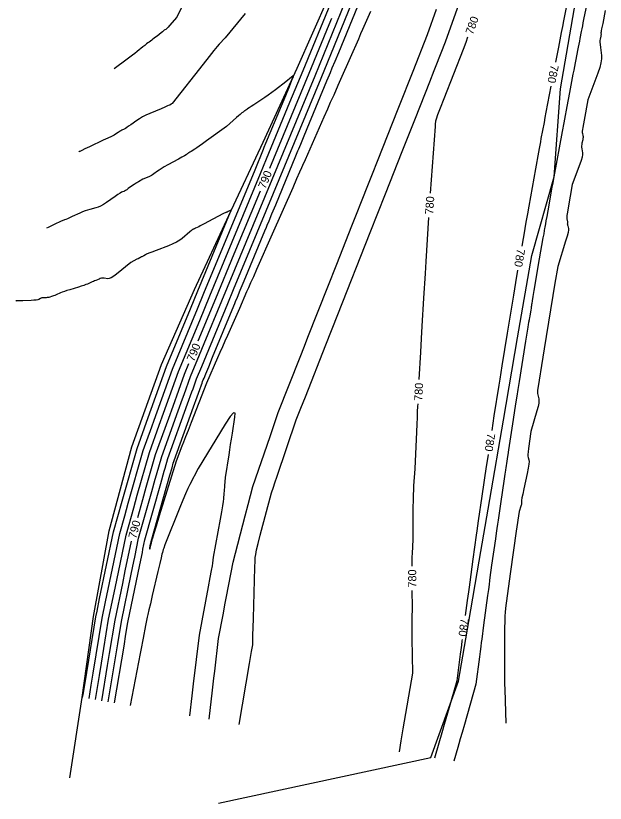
# Model space of a CAD drawing. Extents: x -26 to 1809989, y -25 to 828749.
# Drawn here: x 1809519.1 to 1809881.8, y 826839.3 to 827324 of the extents above; entities that cross this region are included whole.
import ezdxf

# ---------------------------------------------------------------- set-up
doc = ezdxf.new("R2010")
doc.units = 0
for name, color, linetype in [('DESIGN - CONTOURS - Index with Text', 7, 'Continuous'), ('DESIGN - CONTOURS - Intermediate with optional Text', 7, 'Continuous'), ('DESIGN - ROW - Slope Lines', 7, 'Continuous')]:
    doc.layers.add(name, color=color, linetype=linetype)

msp = doc.modelspace()

# ---------------------------------------------------------------- linework, layer by layer
at = {"layer": 'DESIGN - CONTOURS - Index with Text'}
for points in [[(1809870.88, 827393.4), (1809869.78, 827388.6), (1809867.7, 827378.36), (1809867.16, 827375.72), (1809866.44, 827372.18), (1809864.45, 827362.41), (1809858.96, 827335.44), (1809856.09, 827320.79), (1809855.43, 827317.43), (1809854.68, 827313.61), (1809852.93, 827304.59), (1809851.13, 827295.37)], [(1809624.52, 827336.19), (1809618.16, 827323.09), (1809613.69, 827318), (1809612.83, 827317.03), (1809612.15, 827316.3), (1809611.66, 827315.82), (1809611.35, 827315.57), (1809610.78, 827315.23), (1809610.48, 827315.03), (1809610, 827314.67), (1809609.33, 827314.15), (1809608.49, 827313.48), (1809606, 827311.48), (1809605.1, 827310.76), (1809604.28, 827310.12), (1809603.53, 827309.55), (1809602.86, 827309.06), (1809601.17, 827307.84), (1809600.45, 827307.3), (1809599.57, 827306.62), (1809598.51, 827305.77), (1809597.27, 827304.78), (1809593.77, 827301.93), (1809592.4, 827300.83), (1809590.92, 827299.69), (1809589.35, 827298.51), (1809587.67, 827297.28), (1809579.57, 827291.43)], [(1809675.33, 827230.16), (1809699.53, 827288.67), (1809711.85, 827318.62), (1809713.49, 827322.6)], [(1809774.31, 827214.89), (1809777.26, 827255.78), (1809777.37, 827257.13), (1809777.54, 827259.23), (1809777.89, 827260.46), (1809778.86, 827263.19), (1809780.47, 827267.42), (1809782.7, 827273.15), (1809794.58, 827303.37), (1809796.14, 827307.75), (1809797.34, 827311.12)], [(1809848.26, 827280.65), (1809845.29, 827264.67), (1809844.66, 827261.29), (1809844.11, 827258.32), (1809842.26, 827248.42), (1809841.9, 827246.44), (1809841.52, 827244.39), (1809841.12, 827242.28), (1809840.72, 827240.1), (1809838.81, 827229.75), (1809834.72, 827206.74), (1809833.89, 827202.09), (1809833.17, 827198.02), (1809832.55, 827194.52), (1809832.03, 827191.59), (1809830.38, 827182.26)], [(1809631.4, 827123.89), (1809642.2, 827150.05), (1809653.51, 827177.41), (1809669.6, 827216.3)], [(1809767.38, 827100.1), (1809768.32, 827117.05), (1809768.77, 827125.29), (1809769.19, 827132.97), (1809770.14, 827150.22), (1809771.1, 827165.43), (1809771.55, 827172.66), (1809773.26, 827199.93)], [(1809827.87, 827167.47), (1809826.6, 827159.9), (1809825.92, 827155.84), (1809825.27, 827151.95), (1809824.65, 827148.24), (1809821.36, 827128.55), (1809818.18, 827108.51), (1809817.51, 827104.34), (1809816.89, 827100.4), (1809816.3, 827096.71), (1809813.28, 827077.68), (1809811.93, 827068.75)], [(1809594.14, 827015.2), (1809597.26, 827026.23), (1809599.4, 827033.82), (1809605.1, 827054), (1809613.18, 827076.38), (1809615.86, 827083.81), (1809622.97, 827103.48), (1809625.67, 827110.02)], [(1809762.98, 826985.21), (1809762.99, 826988.14), (1809763.04, 826990.96), (1809763.12, 826993.13), (1809763.54, 827001.76), (1809763.68, 827021.65), (1809763.73, 827025.65), (1809763.81, 827029.16), (1809763.92, 827032.17), (1809764.06, 827034.67), (1809764.81, 827045.2), (1809765.79, 827067.97), (1809766, 827072.61), (1809766.19, 827076.75), (1809766.36, 827080.4), (1809766.52, 827083.56), (1809766.6, 827085.12)], [(1809809.7, 827053.92), (1809809.14, 827050.17), (1809808.6, 827046.59), (1809805.86, 827028.32), (1809803.68, 827013.2), (1809803.23, 827010.05), (1809802.8, 827007.06), (1809802.4, 827004.25), (1809800.3, 826989.64), (1809798.39, 826975.41), (1809797.98, 826972.42), (1809797.6, 826969.53), (1809797.22, 826966.75), (1809796.86, 826964.07), (1809795.63, 826954.92)], [(1809572.06, 826902.41), (1809575.61, 826924.05), (1809576.83, 826931.48), (1809580.18, 826951.94), (1809584.87, 826974.66), (1809586.47, 826982.38), (1809590.26, 827000.72)], [(1809755.13, 826870.91), (1809756.31, 826877.84), (1809757.55, 826885.12), (1809763.39, 826919.43), (1809763.02, 826940.68), (1809762.95, 826944.85), (1809762.92, 826948.27), (1809762.92, 826950.93), (1809762.95, 826952.83), (1809763.16, 826959.94), (1809763.08, 826970.21)], [(1809793.69, 826940.04), (1809793.6, 826939.33), (1809793.25, 826936.62), (1809792.89, 826933.85), (1809792.53, 826931.03), (1809790.41, 826914.63), (1809785.75, 826898.36), (1809784.74, 826894.85), (1809783.73, 826891.31), (1809782.71, 826887.73), (1809781.67, 826884.12), (1809776.82, 826867.18)]]:
    msp.add_lwpolyline(points, dxfattribs=at)
at = {"layer": 'DESIGN - CONTOURS - Intermediate with optional Text'}
for points in [[(1809656.58, 826887.87), (1809662.97, 826925.42), (1809664.22, 826932.77), (1809664.93, 826936.9), (1809664.89, 826938.94), (1809664.91, 826940.16), (1809664.98, 826942.94), (1809665.1, 826947.28), (1809665.27, 826953.19), (1809666.2, 826984.39), (1809666.19, 826984.81), (1809666.2, 826985.04), (1809666.22, 826985.55), (1809666.31, 826987.42), (1809666.47, 826990.65), (1809666.71, 826992.42), (1809667.3, 826995.28), (1809668.24, 826999.24), (1809669.54, 827004.3), (1809676.44, 827030.48), (1809677.6, 827033.89), (1809678.5, 827036.53), (1809679.89, 827040.61), (1809691.71, 827075.24), (1809694.56, 827082.48), (1809697.29, 827089.4), (1809709.9, 827121.41), (1809717.28, 827140.1), (1809737.2, 827190.53), (1809746.65, 827214.44), (1809756.94, 827240.49), (1809765.02, 827260.96), (1809773.77, 827283.23), (1809776.54, 827290.27), (1809777.79, 827293.47), (1809783.47, 827307.9), (1809793.98, 827337.47)], [(1809568.11, 826903.09), (1809570.57, 826918.04), (1809571.79, 826925.47), (1809576.24, 826952.64), (1809579.61, 826968.93), (1809581.21, 826976.69), (1809586.94, 827004.38), (1809591.7, 827021.25), (1809593.85, 827028.88), (1809601.3, 827055.26), (1809607.36, 827072.02), (1809610.05, 827079.48), (1809619.27, 827105), (1809632.26, 827136.46), (1809638.51, 827151.61), (1809652.27, 827184.87), (1809669.68, 827226.96), (1809673.43, 827236.04), (1809687.78, 827270.72), (1809695.85, 827290.23), (1809712.96, 827331.83)], [(1809576, 826901.73), (1809580.65, 826930.07), (1809581.86, 826937.49), (1809584.12, 826951.24), (1809590.14, 826980.39), (1809591.73, 826988.07), (1809592.31, 826990.88), (1809594.69, 827002.42), (1809602.82, 827031.21), (1809604.95, 827038.75), (1809605.72, 827041.51), (1809608.9, 827052.75), (1809619.01, 827080.75), (1809621.67, 827088.13), (1809622.65, 827090.84), (1809626.67, 827101.96), (1809632.14, 827115.22), (1809635.03, 827122.2), (1809645.88, 827148.49), (1809703.22, 827287.11), (1809722.06, 827332.93)], [(1809579.94, 826901.06), (1809585.69, 826936.08), (1809586.9, 826943.5), (1809588.06, 826950.54), (1809595.41, 826986.12), (1809596.98, 826993.76), (1809597.37, 826995.64), (1809598.57, 827001.45), (1809608.37, 827036.18), (1809610.49, 827043.69), (1809611.03, 827045.58), (1809612.7, 827051.5), (1809624.83, 827085.11), (1809627.49, 827092.45), (1809628.17, 827094.35), (1809630.37, 827100.44), (1809633.53, 827108.1), (1809636.41, 827115.07), (1809649.56, 827146.94), (1809653.13, 827155.54), (1809677.63, 827214.79), (1809706.9, 827285.55), (1809725.76, 827331.42)], [(1809737.37, 827326.69), (1809732.43, 827315.46), (1809731.26, 827312.81), (1809729.87, 827309.64), (1809728.26, 827305.97), (1809726.42, 827301.8), (1809717.34, 827281.13), (1809714.72, 827275.21), (1809713.92, 827273.4), (1809712.64, 827270.51), (1809710.89, 827266.54), (1809708.65, 827261.49), (1809697.12, 827235.4), (1809695.56, 827231.88), (1809694.93, 827230.45), (1809693.71, 827227.69), (1809691.9, 827223.59), (1809689.5, 827218.15), (1809676.9, 827189.66), (1809667.21, 827167.73), (1809665.27, 827163.35), (1809663.61, 827159.6), (1809662.24, 827156.49), (1809661.14, 827154.01), (1809656.68, 827143.92), (1809649.33, 827127.25), (1809647.77, 827123.71), (1809646.24, 827120.23), (1809644.73, 827116.82), (1809643.25, 827113.46), (1809636.41, 827097.96), (1809626.97, 827073.59), (1809625.1, 827068.77), (1809623.55, 827064.75), (1809622.3, 827061.55), (1809621.37, 827059.15), (1809617.76, 827049.83), (1809607.42, 827016.2), (1809605.48, 827009.87), (1809604.07, 827005.29), (1809603.2, 827002.46), (1809602.87, 827001.38), (1809602.58, 827000.44), (1809602.43, 826999.79), (1809602.38, 826999.59), (1809602.3, 826999.24), (1809602.19, 826998.75), (1809602.05, 826998.13), (1809601.62, 826996.28), (1809601.5, 826995.78), (1809601.47, 826995.65), (1809601.51, 826995.91), (1809601.64, 826996.54), (1809602.09, 826998.73), (1809602.24, 826999.45), (1809602.35, 826999.97), (1809602.41, 827000.29), (1809602.44, 827000.4), (1809602.45, 827000.47), (1809612.12, 827034.72), (1809613.93, 827041.16), (1809615.24, 827045.79), (1809616.04, 827048.63), (1809616.33, 827049.65), (1809616.5, 827050.25), (1809628.42, 827083.26), (1809630.66, 827089.48), (1809632.29, 827093.98), (1809633.3, 827096.78), (1809633.69, 827097.86), (1809634.07, 827098.92), (1809634.49, 827099.94), (1809634.92, 827100.97), (1809636.02, 827103.64), (1809637.8, 827107.94), (1809640.24, 827113.88), (1809653.25, 827145.38), (1809653.9, 827146.96), (1809654.37, 827148.08), (1809655.48, 827150.76), (1809657.23, 827155.01), (1809659.64, 827160.82), (1809672.36, 827191.58), (1809673.3, 827193.85), (1809673.81, 827195.08), (1809674.93, 827197.8), (1809676.67, 827202.01), (1809679.03, 827207.71), (1809691.47, 827237.79), (1809692.72, 827240.81), (1809693.28, 827242.16), (1809694.42, 827244.92), (1809696.15, 827249.09), (1809698.46, 827254.67), (1809710.58, 827283.99), (1809712.1, 827287.69), (1809712.7, 827289.14), (1809713.84, 827291.92), (1809715.53, 827296.03), (1809717.77, 827301.46), (1809729.47, 827329.91)], [(1809870.37, 827331.35), (1809868.48, 827321.68), (1809868.09, 827319.67), (1809867.72, 827317.76), (1809867.37, 827315.97), (1809867.04, 827314.3), (1809866.2, 827309.98), (1809865.87, 827308.3), (1809865.53, 827306.52), (1809865.16, 827304.62), (1809864.76, 827302.61), (1809863.69, 827297.1), (1809863.28, 827294.99), (1809862.85, 827292.79), (1809862.41, 827290.5), (1809861.94, 827288.12), (1809859.75, 827276.81), (1809858.15, 827268.25), (1809857.72, 827265.9), (1809857.09, 827262.52), (1809856.28, 827258.12), (1809855.27, 827252.69), (1809850.14, 827224.95), (1809850.08, 827224.58), (1809850.06, 827224.48), (1809850.04, 827224.35), (1809850.01, 827224.19), (1809849.97, 827223.99), (1809849.87, 827223.41), (1809849.75, 827222.71), (1809849.45, 827221.05), (1809848.99, 827218.43), (1809848.35, 827214.85), (1809846.43, 827204.02), (1809845.79, 827200.41), (1809845.31, 827197.7), (1809845, 827195.9), (1809844.84, 827195), (1809844.63, 827193.82), (1809844.5, 827193.08), (1809844.26, 827191.77), (1809843.93, 827189.87), (1809843.49, 827187.38), (1809841.2, 827174.44), (1809837.94, 827154.92), (1809837.33, 827151.24), (1809836.88, 827148.56), (1809836.6, 827146.89), (1809836.49, 827146.23), (1809836.42, 827145.79), (1809836.37, 827145.48), (1809836.27, 827144.88), (1809836.12, 827143.98), (1809835.92, 827142.79), (1809835.32, 827139.22), (1809835.12, 827138.03), (1809834.98, 827137.17), (1809834.89, 827136.61), (1809834.85, 827136.37), (1809834.81, 827136.15), (1809834.76, 827135.85), (1809834.64, 827135.11), (1809834.44, 827133.93), (1809834.17, 827132.31), (1809832.74, 827123.73), (1809828.81, 827098.95), (1809828.03, 827094.01), (1809827.36, 827089.82), (1809826.82, 827086.38), (1809826.39, 827083.68), (1809824.68, 827072.85), (1809822.29, 827056.92), (1809821.83, 827053.85), (1809821.47, 827051.47), (1809821.21, 827049.76), (1809821.06, 827048.74), (1809820.79, 827046.93), (1809820.64, 827045.93), (1809820.39, 827044.27), (1809820.05, 827041.96), (1809819.6, 827038.99), (1809817.3, 827023.62), (1809815.85, 827013.5), (1809815.52, 827011.17), (1809815.14, 827008.5), (1809814.71, 827005.5), (1809814.23, 827002.16), (1809811.89, 826985.82), (1809810.88, 826978.29), (1809810.62, 826976.39), (1809810.29, 826973.91), (1809809.87, 826970.85), (1809809.38, 826967.21), (1809806.92, 826948.9), (1809805.81, 826940.32), (1809805.54, 826938.26), (1809805.22, 826935.76), (1809804.84, 826932.81), (1809804.4, 826929.41), (1809802.23, 826912.54), (1809795.14, 826887.82), (1809793.75, 826882.96), (1809792.61, 826878.97), (1809791.72, 826875.85), (1809791.07, 826873.6), (1809788.65, 826865.15)], [(1809660.17, 827325.41), (1809648.02, 827310.46), (1809644.15, 827306.41), (1809642.91, 827305.01), (1809640.86, 827302.51), (1809638, 827298.94), (1809634.33, 827294.28), (1809615.28, 827270.02), (1809614.58, 827269.49), (1809614.44, 827269.39), (1809614.33, 827269.31), (1809614.26, 827269.26), (1809614.21, 827269.23), (1809614.12, 827269.2), (1809614.09, 827269.18), (1809614.05, 827269.17), (1809614.02, 827269.15), (1809613.89, 827269.07), (1809613.53, 827268.92), (1809612.53, 827268.49), (1809610.89, 827267.79), (1809608.6, 827266.81), (1809601.64, 827263.86), (1809599.18, 827262.76), (1809597.02, 827261.69), (1809595.16, 827260.63), (1809593.59, 827259.6), (1809589.82, 827256.89), (1809588.51, 827255.96), (1809587.42, 827255.22), (1809586.54, 827254.65), (1809585.87, 827254.27), (1809584.39, 827253.5), (1809583.83, 827253.2), (1809583.26, 827252.87), (1809582.68, 827252.52), (1809582.1, 827252.14), (1809580.52, 827251.11), (1809579.61, 827250.58), (1809578.04, 827249.78), (1809575.83, 827248.7), (1809572.96, 827247.34), (1809564.46, 827243.36), (1809561.66, 827242.05), (1809559.66, 827241.11), (1809558.45, 827240.55), (1809558.04, 827240.35), (1809557.94, 827240.29)], [(1809637.99, 826891.07), (1809640.12, 826908.94), (1809641, 826916.38), (1809641.5, 826920.54), (1809643.9, 826940.63), (1809646.66, 826955.31), (1809647.99, 826962.38), (1809648.8, 826966.65), (1809652.79, 826987.77), (1809660.31, 827016.27), (1809662.14, 827023.24), (1809665.04, 827034.24), (1809675.55, 827064.97), (1809677.88, 827071.81), (1809680.61, 827079.8), (1809694.01, 827113.8), (1809696.74, 827120.74), (1809698.85, 827126.09), (1809711.13, 827157.17), (1809716.64, 827171.13), (1809725.94, 827194.67), (1809729.18, 827202.89), (1809731.45, 827208.62), (1809736.58, 827221.61), (1809738.17, 827225.63), (1809742.09, 827235.57), (1809753.97, 827265.64), (1809758.01, 827275.91), (1809760.25, 827281.62), (1809763.52, 827289.95), (1809772.35, 827312.43), (1809777.92, 827328.08)], [(1809881.79, 827327.27), (1809880.22, 827319.21), (1809879.58, 827315.91), (1809879.37, 827314.81), (1809879.23, 827314), (1809879.16, 827313.46), (1809879.15, 827313.21), (1809879.21, 827312.92), (1809879.21, 827312.74), (1809879.18, 827312.42), (1809879.1, 827311.96), (1809878.99, 827311.36), (1809878.63, 827309.59), (1809878.54, 827308.77), (1809878.54, 827307.66), (1809878.64, 827306.25), (1809878.82, 827304.54), (1809879.44, 827299.58), (1809879.47, 827297.51), (1809879.12, 827295.02), (1809878.38, 827292.1), (1809877.25, 827288.76), (1809871.09, 827272.19), (1809868.79, 827259.78), (1809867.93, 827255.13), (1809867.74, 827253.97), (1809867.65, 827253), (1809867.64, 827252.22), (1809867.72, 827251.62), (1809868.06, 827250.29), (1809868.15, 827249.76), (1809868.16, 827249.15), (1809868.09, 827248.46), (1809867.94, 827247.7), (1809867.44, 827245.57), (1809867.3, 827244.76), (1809867.24, 827243.92), (1809867.27, 827243.05), (1809867.38, 827242.15), (1809867.81, 827239.71), (1809867.82, 827238.58), (1809867.55, 827237.01), (1809866.98, 827235.01), (1809866.13, 827232.57), (1809861.48, 827220.16), (1809858.95, 827205.85), (1809858.49, 827203.11), (1809858.2, 827201.05), (1809858.07, 827199.66), (1809858.11, 827198.94), (1809858.43, 827197.91), (1809858.53, 827197.54), (1809858.59, 827197.23), (1809858.61, 827196.96), (1809858.59, 827196.74), (1809858.47, 827196.23), (1809858.46, 827195.98), (1809858.49, 827195.65), (1809858.58, 827195.21), (1809858.73, 827194.68), (1809859.17, 827193.14), (1809859.19, 827192.21), (1809858.91, 827190.6), (1809858.32, 827188.28), (1809857.43, 827185.28), (1809852.56, 827169.64), (1809850.85, 827159.38), (1809844.13, 827118.92), (1809843.33, 827113.92), (1809840.26, 827094.5), (1809840.14, 827093.47), (1809840.12, 827092.48), (1809840.19, 827091.53), (1809840.36, 827090.61), (1809840.92, 827088.21), (1809841.01, 827087.07), (1809840.84, 827085.48), (1809840.43, 827083.42), (1809839.77, 827080.89), (1809836.08, 827068.03), (1809834.53, 827057.65), (1809834.27, 827055.64), (1809834.14, 827054.04), (1809834.15, 827052.87), (1809834.29, 827052.11), (1809834.86, 827050.65), (1809834.95, 827049.72), (1809834.79, 827048.03), (1809834.39, 827045.58), (1809833.75, 827042.37), (1809831.71, 827032.78), (1809831.04, 827029.6), (1809830.57, 827027.23), (1809830.3, 827025.68), (1809830.22, 827024.95), (1809830.29, 827024.09), (1809830.28, 827023.72), (1809830.21, 827023.26), (1809830.07, 827022.72), (1809829.86, 827022.08), (1809828.75, 827018.92), (1809827.01, 827006.72), (1809823.48, 826982), (1809820.85, 826962.49), (1809820.46, 826959.43), (1809820.17, 826956.8), (1809819.99, 826954.61), (1809819.91, 826952.85), (1809819.77, 826945.66), (1809819.8, 826937.49), (1809819.89, 826912.73), (1809819.91, 826909.4), (1809820.55, 826888.55)], [(1809564.17, 826903.77), (1809565.53, 826912.02), (1809566.75, 826919.46), (1809572.31, 826953.34), (1809574.34, 826963.2), (1809575.96, 826971.01), (1809583.06, 827005.36), (1809586.14, 827016.27), (1809588.31, 827023.95), (1809597.5, 827056.51), (1809602.72, 827070.94), (1809604.24, 827075.16), (1809615.57, 827106.52), (1809630.87, 827143.59), (1809634.83, 827153.17), (1809666.3, 827229.25), (1809671.51, 827241.85), (1809672.03, 827243.12), (1809673.05, 827245.58), (1809685.18, 827274.9), (1809687.45, 827280.39), (1809689.04, 827284.3), (1809689.97, 827286.62), (1809690.23, 827287.37), (1809690.04, 827287.23), (1809689.68, 827286.95), (1809688.75, 827286.22), (1809685.17, 827283.42), (1809678.87, 827278.48), (1809676.57, 827276.71), (1809674.4, 827275.11), (1809672.37, 827273.67), (1809670.46, 827272.39), (1809665.56, 827269.2), (1809663.91, 827268.12), (1809662.63, 827267.29), (1809661.74, 827266.69), (1809661.23, 827266.33), (1809660.04, 827265.45), (1809659.72, 827265.21), (1809659.4, 827264.98), (1809659.09, 827264.76), (1809658.27, 827264.16), (1809657.83, 827263.81), (1809657.13, 827263.23), (1809656.18, 827262.41), (1809654.97, 827261.36), (1809648.71, 827255.87), (1809636.39, 827246.94), (1809633.97, 827245.19), (1809631.98, 827243.78), (1809630.43, 827242.71), (1809629.32, 827241.98), (1809626.94, 827240.49), (1809626.14, 827239.99), (1809625.55, 827239.61), (1809625.16, 827239.36), (1809624.97, 827239.24), (1809624.73, 827239.07), (1809624.65, 827239), (1809624.57, 827238.94), (1809624.49, 827238.87), (1809624.41, 827238.8), (1809624.22, 827238.61), (1809623.85, 827238.38), (1809622.89, 827237.83), (1809621.34, 827236.97), (1809619.2, 827235.78), (1809612.7, 827232.19), (1809610.47, 827230.94), (1809608.65, 827229.87), (1809607.24, 827228.99), (1809606.23, 827228.3), (1809604.1, 827226.7), (1809603.3, 827226.13), (1809602.51, 827225.63), (1809601.72, 827225.2), (1809600.94, 827224.84), (1809597.32, 827223.33), (1809594.66, 827221.82), (1809594.16, 827221.54), (1809593.77, 827221.33), (1809593.52, 827221.19), (1809593.38, 827221.13), (1809593.18, 827221.06), (1809592.99, 827220.94), (1809592.56, 827220.65), (1809591.9, 827220.19), (1809591, 827219.54), (1809588.28, 827217.59), (1809587.34, 827216.93), (1809586.58, 827216.44), (1809586, 827216.09), (1809585.59, 827215.91), (1809584.72, 827215.63), (1809584.19, 827215.37), (1809583.25, 827214.79), (1809581.91, 827213.91), (1809580.15, 827212.71), (1809574.92, 827209.1), (1809573.03, 827207.87), (1809571.3, 827206.9), (1809569.72, 827206.18), (1809568.3, 827205.72), (1809564.7, 827204.83), (1809563.3, 827204.44), (1809561.79, 827203.93), (1809560.19, 827203.29), (1809558.48, 827202.53), (1809553.8, 827200.35), (1809552.19, 827199.61), (1809550.88, 827199.02), (1809549.88, 827198.59), (1809549.17, 827198.31), (1809547.69, 827197.78), (1809547.06, 827197.53), (1809546.28, 827197.2), (1809545.36, 827196.78), (1809544.29, 827196.28), (1809538.93, 827193.74), (1809538.08, 827193.35)], [(1809560.23, 826904.45), (1809560.49, 826906.01), (1809561.71, 826913.45), (1809568.37, 826954.04), (1809569.08, 826957.47), (1809570.7, 826965.32), (1809579.18, 827006.34), (1809584.51, 827025.21), (1809593.7, 827057.76), (1809600.58, 827076.8), (1809611.87, 827108.04), (1809626.6, 827143.71), (1809631.14, 827154.73), (1809651.26, 827203.36), (1809651.44, 827203.82), (1809651.56, 827204.13), (1809651.61, 827204.31), (1809651.6, 827204.35), (1809651.48, 827204.28), (1809651.4, 827204.25), (1809651.27, 827204.19), (1809651.08, 827204.11), (1809650.1, 827203.69), (1809649.85, 827203.59), (1809649.64, 827203.49), (1809649.47, 827203.42), (1809649.35, 827203.35), (1809649.09, 827203.21), (1809648.97, 827203.14), (1809648.8, 827203.07), (1809648.58, 827202.97), (1809648.32, 827202.86), (1809646.97, 827202.32), (1809637.34, 827197.11), (1809635.44, 827196.08), (1809633.87, 827195.26), (1809632.62, 827194.62), (1809631.7, 827194.18), (1809629.68, 827193.26), (1809629.01, 827192.96), (1809628.53, 827192.73), (1809628.22, 827192.59), (1809628.1, 827192.53), (1809628.02, 827192.48), (1809627.99, 827192.46), (1809627.96, 827192.44), (1809627.91, 827192.42), (1809627.86, 827192.39), (1809627.67, 827192.24), (1809627.15, 827191.8), (1809626.29, 827191.07), (1809621.49, 827186.95), (1809619.94, 827185.8), (1809618.02, 827184.67), (1809615.72, 827183.55), (1809613.04, 827182.46), (1809605.4, 827179.57), (1809602.84, 827178.59), (1809600.9, 827177.83), (1809599.58, 827177.27), (1809598.87, 827176.94), (1809597.82, 827176.32), (1809597.44, 827176.1), (1809597.09, 827175.9), (1809596.76, 827175.72), (1809596.47, 827175.56), (1809595.74, 827175.18), (1809595.4, 827175), (1809594.32, 827174.46), (1809593.58, 827174.09), (1809589.83, 827172.2), (1809581.08, 827165), (1809579.34, 827163.66), (1809577.86, 827162.73), (1809576.64, 827162.22), (1809575.69, 827162.12), (1809573.49, 827162.4), (1809572.68, 827162.45), (1809571.89, 827162.4), (1809571.11, 827162.24), (1809570.35, 827161.98), (1809568.35, 827161.14), (1809567.59, 827160.83), (1809566.83, 827160.5), (1809566.05, 827160.16), (1809565.25, 827159.82), (1809563.13, 827158.88), (1809562.19, 827158.5), (1809560.95, 827158.06), (1809559.43, 827157.56), (1809557.62, 827156.99), (1809552.41, 827155.4), (1809550.58, 827154.83), (1809548.99, 827154.3), (1809547.66, 827153.82), (1809546.57, 827153.39), (1809544, 827152.29), (1809543.1, 827151.92), (1809542.33, 827151.61), (1809541.68, 827151.36), (1809541.17, 827151.18), (1809539.97, 827150.79), (1809539.51, 827150.66), (1809539, 827150.57), (1809538.45, 827150.51), (1809537.86, 827150.49), (1809536.23, 827150.47), (1809535.64, 827150.44), (1809535.12, 827150.35), (1809534.65, 827150.2), (1809534.23, 827149.99), (1809533.21, 827149.37), (1809532.63, 827149.15), (1809531.66, 827148.99), (1809530.3, 827148.87), (1809528.56, 827148.79), (1809523.4, 827148.64), (1809521.69, 827148.59), (1809520.46, 827148.54), (1809519.69, 827148.5), (1809519.39, 827148.47), (1809519.08, 827148.33)], [(1809626.16, 826893.1), (1809627.64, 826905.47), (1809628.52, 826912.91), (1809632.08, 826942.73), (1809637.73, 826972.61), (1809638.8, 826978.32), (1809639.59, 826982.62), (1809640.1, 826985.53), (1809640.33, 826987.04), (1809640.75, 826990.81), (1809645.03, 827014.19), (1809645.84, 827018.73), (1809646.45, 827022.33), (1809646.86, 827025), (1809647.06, 827026.73), (1809647.33, 827030.08), (1809647.44, 827031.32), (1809647.53, 827032.51), (1809647.63, 827033.66), (1809647.73, 827034.76), (1809648.16, 827039.81), (1809650.3, 827053.74), (1809650.78, 827056.82), (1809651.28, 827060.07), (1809651.82, 827063.49), (1809652.39, 827067.1), (1809653.97, 827076.94), (1809654.03, 827079.44), (1809653.06, 827079.55), (1809651.04, 827077.29), (1809647.98, 827072.64), (1809631.26, 827045.38), (1809626.12, 827035.46), (1809624.91, 827032.99), (1809623.48, 827029.81), (1809621.84, 827025.94), (1809619.98, 827021.36), (1809610.78, 826998.37), (1809610.12, 826996.29), (1809609.98, 826995.86), (1809609.85, 826995.44), (1809609.72, 826995.05), (1809609.61, 826994.68), (1809609.3, 826993.72), (1809609.04, 826992.71), (1809608.49, 826990.41), (1809607.65, 826986.81), (1809606.51, 826981.92), (1809603.1, 826967.15), (1809601.95, 826962.16), (1809601.05, 826958.28), (1809600.41, 826955.5), (1809600.02, 826953.84), (1809598.82, 826948.63), (1809597.38, 826940.96), (1809596.97, 826938.81), (1809596.37, 826935.63), (1809595.58, 826931.42), (1809594.59, 826926.19), (1809589.53, 826899.41)]]:
    msp.add_lwpolyline(points, dxfattribs=at)
at = {"layer": 'DESIGN - ROW - Slope Lines'}
for p, q in [((1809692.33, 827291.71), (1809712.14, 827336.97)), ((1809854.25, 827279.05), (1809863.66, 827333.75)), ((1809671.41, 827246.27), (1809692.33, 827291.71)), ((1809850.33, 827224.87), (1809854.25, 827279.05)), ((1809650.09, 827201), (1809671.41, 827246.27)), ((1809836.59, 827176.4), (1809850.33, 827224.87)), ((1809629.07, 827155.61), (1809650.09, 827201)), ((1809827.88, 827125.79), (1809836.59, 827176.4)), ((1809608.74, 827109.33), (1809629.07, 827155.61)), ((1809819.17, 827075.18), (1809827.88, 827125.79)), ((1809590.6, 827058.78), (1809608.74, 827109.33)), ((1809810.77, 827026.31), (1809819.17, 827075.18)), ((1809576.58, 827006.99), (1809590.6, 827058.78)), ((1809804.23, 826988.35), (1809810.77, 827026.31)), ((1809566.86, 826954.3), (1809576.58, 827006.99)), ((1809797.84, 826951.19), (1809804.23, 826988.35)), ((1809559.86, 826904.51), (1809566.86, 826954.3)), ((1809791.52, 826914.44), (1809797.84, 826951.19)), ((1809774.5, 826867.58), (1809791.52, 826914.44)), ((1809552.34, 826855.07), (1809559.86, 826904.51)), ((1809643.79, 826839.34), (1809774.5, 826867.58))]:
    msp.add_line(p, q, dxfattribs=at)

# ---------------------------------------------------------------- texts
at = {"layer": 'DESIGN - CONTOURS - Index with Text'}
for s, rotation, p in [('780', 70.3958, (1809800.31, 827312.01)), ('780', 258.9853, (1809848.32, 827294.04)), ('790', 67.5284, (1809672.61, 827217.05)), ('780', 85.9849, (1809775.87, 827201.59)), ('780', 260.3855, (1809827.59, 827180.86)), ('790', 67.5688, (1809628.69, 827110.77)), ('780', 87.0087, (1809769.19, 827086.83)), ('780', 261.4432, (1809809.19, 827067.3)), ('790', 74.9855, (1809593.06, 827001.87)), ('780', 90.3672, (1809765.56, 826972.07)), ('780', 262.5735, (1809792.9, 826953.41))]:
    msp.add_text(s, height=5, rotation=rotation, dxfattribs=at).set_placement(p)

doc.saveas('drawing.dxf')
